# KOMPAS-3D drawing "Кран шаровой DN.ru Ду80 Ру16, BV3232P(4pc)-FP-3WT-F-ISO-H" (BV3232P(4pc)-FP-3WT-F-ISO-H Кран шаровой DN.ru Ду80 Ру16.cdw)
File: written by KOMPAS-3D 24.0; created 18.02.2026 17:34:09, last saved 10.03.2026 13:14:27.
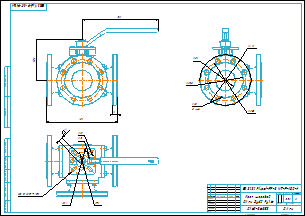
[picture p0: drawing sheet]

Document properties: Автор: R2D2; Форматы листов документа: A2; Полное имя файла: BV3232P(4pc)-FP-3WT-F-ISO-H Кран шаровой DN.ru Ду80 Ру16.m3d; Масса: 39.1; Наименование: Кран шаровой DN.ru Ду80 Ру16; Количество листов документа: 1; Примечание: D160-36353

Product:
- Part/product: Кран шаровой DN.ru Ду80 Ру16  | designation BV3232P(4pc)-FP-3WT-F-ISO-H
    Масса: 39.1
    Раздел спецификации: Прочие изделия
    Примечание: D160-36353

Views: Проекционный вид 2
Referenced files in E:\Работа\Зайцев\BV3232P(4pc)-FP-3WL-F-ISO-H Кран шаровой DN.ru Ду15-100 Ру16\DN80\: BV3232P(4pc)-FP-3WL-F-ISO-H Кран шаровой DN.ru Ду80 Ру16.m3d
Referenced files in E:\Работа\Зайцев\Для компаса\: чертеж DN.ru А3.cdt
Referenced files in E:\Работа\Зайцев\BV3232P(4pc)-FP-3WT-F-ISO-H Кран шаровой DN.ru Ду15-100 Ру16\DN80\: BV3232P(4pc)-FP-3WT-F-ISO-H Кран шаровой DN.ru Ду80 Ру16.m3d
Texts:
  BV3232P(4pc)-FP-3WT-F-ISO-H
  чертеж DN.ru А3.cdt
  Кран шаровой
  DN.ru Ду80 Ру16
  Кран шаровой DN.ru Ду80 Ру16
  BV3232P(4pc)-FP-3WT-F-ISO-H Кран шаровой DN.ru Ду80 Ру16
Dimensions and other numbers on the sheet: 0; 3; 4; 200; 160; 138; 18; 8 отв.; 80; 1:2; 1; 2; 39,1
